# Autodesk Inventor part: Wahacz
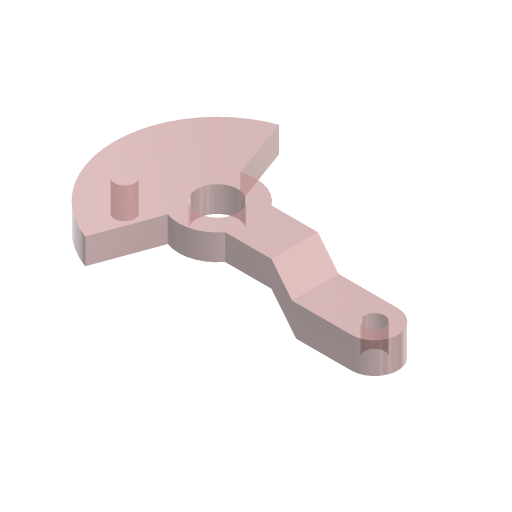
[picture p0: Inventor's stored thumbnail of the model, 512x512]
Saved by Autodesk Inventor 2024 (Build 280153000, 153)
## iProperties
Company: ATC
Shininess: 20.0
Angle Display Precision: 2
Document Length Units: 11269
Document Angle Units: 11279
Document Time Units: 11290
Document Mass Units: 11283
Document Length Units Precision: 3
Document Angle Units Precision: 2
Created: 2023-03
Part Number: Wahacz
Material: Stal węglowa
Document SubType Name: Modelowanie
Designer: Andrzej Jaskulski
Density: 7.87 g/cm^3
Stock Number: Wahacz
Mass: 326.35 g
Surface Area: 107.803 cm^2
Volume: 32.635 cm^3
Appearance: Stal
Checked By: A.J.
Engr Approved By: Andrzej Jaskulski
Mfg Approved By: Andrzej Jaskulski
Authority: A.J.
Density: 0.0
Volumn: 0.0
Area: 0.0
PropertySet Name: Model Information
Control State: 0
Master: False
Checked Out: False
Title: A.J.: Kurs R2024-MEP
Author: Andrzej Jaskulski
Revision Number: 1/24
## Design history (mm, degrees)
sketch "Szkic1"
  geometry: L1 (36.371, 18.985)-(54.371, 18.985); L2 (36.371, 0.985)-(54.371, 0.985); L3 (19.241, -4.11)-(10.691, -27.603); L4 (19.241, 24.081)-(10.691, 47.573); L5 (-41.915, 9.985)-(91.63, 9.985); L6 (54.371, 0.985)-(54.371, 18.985); L7 (19.241, -4.11)-(24.371, 9.985); L8 (19.241, 24.081)-(24.371, 9.985); C1 r 8 at (24.371, 9.985); C2 r 4 at (-11.629, 9.985); A1 r 15 centre (24.371, 9.985) between (19.241, 24.081) and (19.241, -4.11); A2 r 40 centre (24.371, 9.985) between (10.691, 47.573) and (10.691, -27.603)
  constraints: 16 end point, 6 point on circle, 4 centre point, 2 collinear, 2 point on line, 1 coincident, 1 concentric, 1 horizontal, 1 parallel, 1 perpendicular, 1 tangent, 3 other
  dimensions: "d4" = 40 radius of A2; "d5" = 30 diameter of A1; "d6" = 16 diameter of C1; "d7" = 8 diameter of C2; "d22" = 140 deg angle of L3 L4; "d23" = 30 distance from line of L6 C1.centre; "d24" = 18 distance of L2.end L1.end
extrude "Wyciągnięcie proste1" new body sketch "Szkic1" distance "d2" = 10; taper "d3" = 0 deg
extrude "Wyciągnięcie proste2" join sketch "Szkic1" distance "d8" = 12; taper "d9" = 0 deg
extrude "Wyciągnięcie proste3" cut sketch "Szkic1" extent not by distance; stored distance "d12" = 12; taper "d13" = 0 deg
sketch "Szkic5"
  geometry: L1 (30, 0)-(30, 10) reference; L2 (30, 10)-(38, 0); L3 (38, 0)-(70, 0); L4 (70, 0)-(70, -12); L5 (70, -12)-(39.6, -12); L6 (39.6, -12)-(30, 0); L7 (0, -16.4)-(0, 14.4) reference
  constraints: 10 end point, 3 perpendicular, 1 parallel, 1 point on line
  dimensions: "d19" = 12 distance between parallel lines of L3 L5; "d20" = 38 distance from line of L2.end L7; "d28" = 70 distance between parallel lines of L4 L7
extrude "Wyciągnięcie proste5" join sketch "Szkic5" stored distance "d25" = 17.57962; taper "d26" = 0 deg
fillet "Zaokrąglenie1" dims "d27" = 9
sketch "Szkic6"
  geometry: A1 r 9 centre (23, 9) between (23, 0) and (23, 18) reference; 1 further point
hole "Otwór1" sketch "Szkic6" diameter "d30" = 8; stored, may be unused: countersink angle "d34" = 82 deg, drill point angle "d36" = 118 deg; dims "d31" = 6, "d32" = 4, "d33" = 2, "d35" = 8
node "Bryła1"
node "Korpusy bryłowe"
node "Korpusy powierzchniowe"
node "Początek"
node "Oś konstrukcyjna1"
node "Płaszczyzna konstrukcyjna2"
node "Płaszczyzna YZ"
node "Płaszczyzna XZ"
node "Płaszczyzna XY"
node "Oś X"
node "Oś Y"
node "Oś Z"
node "Punkt środkowy"
other parameters: "d0" = 110 deg, "d18" = 0
